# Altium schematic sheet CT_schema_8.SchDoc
size 287 x 160 mm
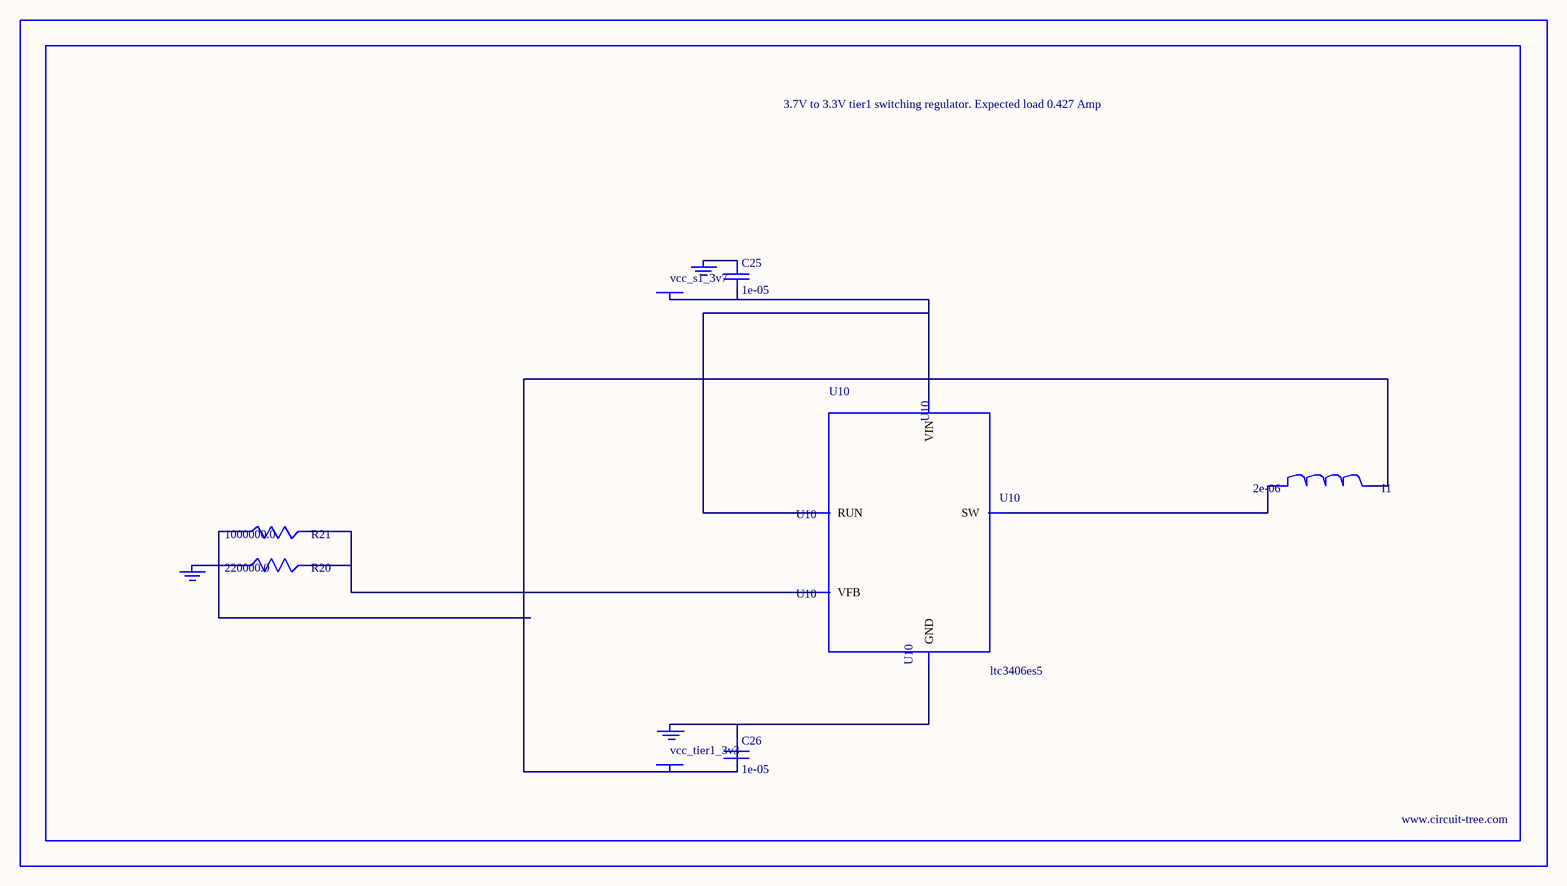
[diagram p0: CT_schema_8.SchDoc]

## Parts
BORDER7  (no value)
C25  1e-05  [C0805]
C26  1e-05  [C0805]
GND_INSTANCE_7_0  (no value)
GND_INSTANCE_7_1  (no value)
GND_INSTANCE_7_2  (no value)
I1  2e-06  [WE-HCI_7030/7040/7050]
POWER_INSTANCE_7_0  vcc_tier1_3v3
POWER_INSTANCE_7_1  vcc_s1_3v7
R20  220000.0  [R0603]
R21  1000000.0  [R0603]
U10  ltc3406es5  [TSOT-23-5]

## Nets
NetC25_1: C25.1 GND_INSTANCE_7_1.0(GND)
NetC25_2: C25.2 POWER_INSTANCE_7_1.0(PWR) U10.1(RUN) U10.4(VIN)
NetC26_1: C26.1 GND_INSTANCE_7_0.0(GND) U10.2(GND)
NetC26_2: C26.2 I1.2 POWER_INSTANCE_7_0.0(PWR) R21.1
NetGND_INSTANCE_7_2_0: GND_INSTANCE_7_2.0(GND) R20.1
NetI1_1: I1.1 U10.3(SW)
NetR20_2: R20.2 R21.2 U10.5(VFB)

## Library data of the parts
BORDER7 = BORDER_PAGE7
C25 C26 = C0805C106K8RACTU
GND_INSTANCE_7_0-GND_INSTANCE_7_2 = GND
I1 = 744314200
POWER_INSTANCE_7_0 POWER_INSTANCE_7_1 = PWR
R20 = RC0603JR-07220KL
R21 = RC0603JR-071ML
